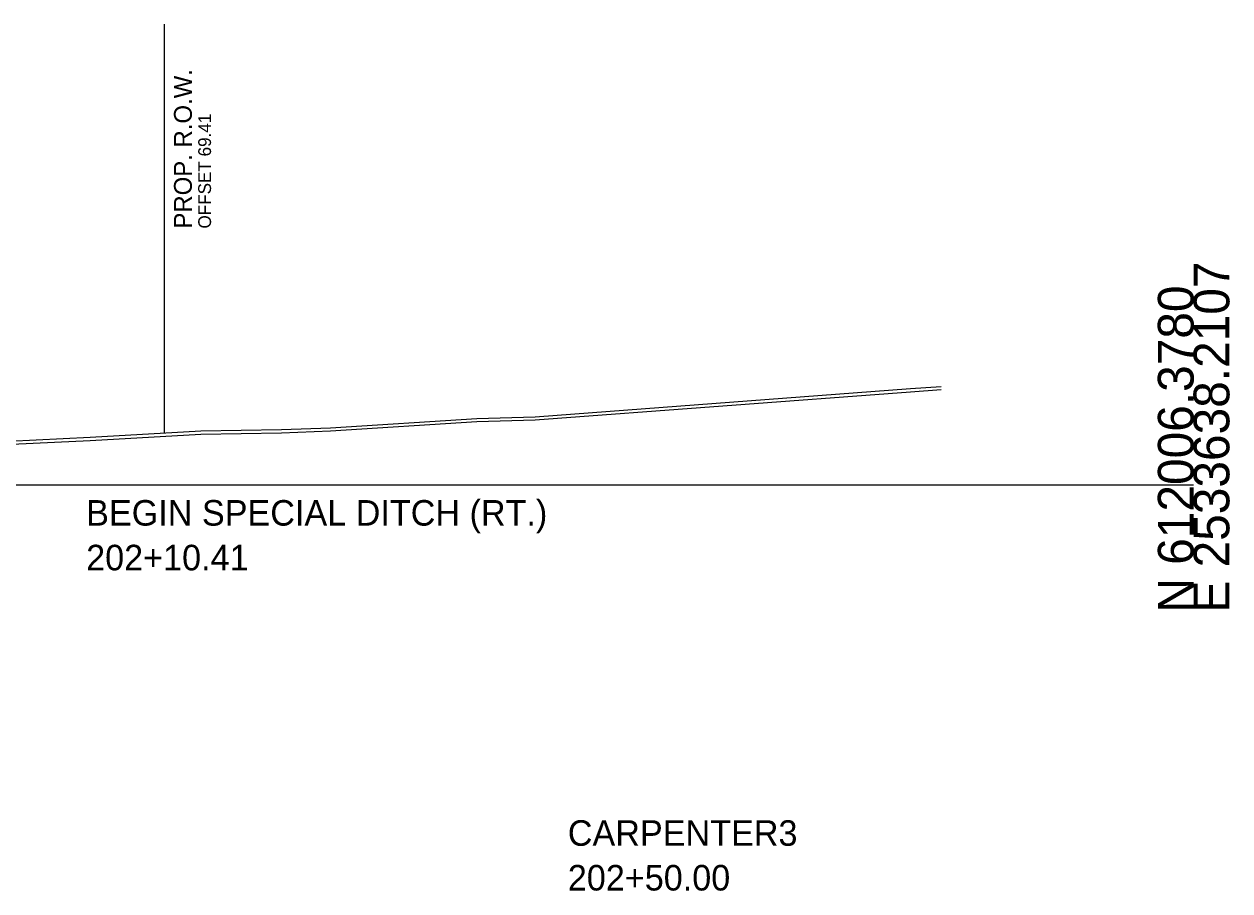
# Model space of a CAD drawing. Extents: x -120 to 2876, y -25 to 8560.
# Drawn here: x 208.4 to 302.8, y 4968.2 to 5036.1 of the extents above; entities that cross this region are included whole.
import ezdxf

# ---------------------------------------------------------------- set-up
doc = ezdxf.new("R2010")
doc.units = 0
for name, color, linetype in [('DESIGN - ROW - Right-of-Way and Easement Labels', 7, 'Continuous'), ('DESIGN - ROW - Right-of-Way Linework', 7, 'Continuous'), ('DESIGN - SHEET - Light Grid', 7, 'Continuous'), ('DESIGN - TRANSPORTATION - Text', 7, 'Continuous'), ('DESIGN - TYPICAL - Warning Text', 7, 'Continuous'), ('SURVEY - GROUND - Bottom of Topsoil Layer', 7, 'Continuous'), ('SURVEY - GROUND - Top of Ground', 7, 'Continuous')]:
    doc.layers.add(name, color=color, linetype=linetype)

msp = doc.modelspace()

# ---------------------------------------------------------------- linework, layer by layer
at = {"layer": 'DESIGN - ROW - Right-of-Way Linework'}
msp.add_line((219.413, 5004.063), (219.413, 5036.063), dxfattribs=at)
at = {"layer": 'DESIGN - SHEET - Light Grid'}
msp.add_line((150, 5000), (300, 5000), dxfattribs=at)
at = {"layer": 'SURVEY - GROUND - Bottom of Topsoil Layer'}
for p, q in [((248.444, 5005.081), (277.826, 5007.286)), ((277.826, 5007.286), (280.241, 5007.452)), ((232.411, 5004.225), (243.885, 5004.955)), ((243.885, 5004.955), (248.444, 5005.081)), ((213.608, 5003.475), (222.261, 5003.98)), ((222.261, 5003.98), (228.586, 5004.074)), ((228.586, 5004.074), (232.411, 5004.225)), ((205.127, 5003.074), (213.608, 5003.475))]:
    msp.add_line(p, q, dxfattribs=at)
at = {"layer": 'SURVEY - GROUND - Top of Ground'}
msp.add_lwpolyline([(205.127, 5003.324), (213.608, 5003.725), (222.261, 5004.23), (228.586, 5004.324), (232.411, 5004.475), (243.885, 5005.205), (248.444, 5005.331), (277.826, 5007.536), (280.241, 5007.702)], dxfattribs=at)

# ---------------------------------------------------------------- texts
at = {"layer": 'DESIGN - ROW - Right-of-Way and Easement Labels'}
for s, height, p in [('PROP. R.O.W.', 1.4, (221.563, 5020.063)), ('OFFSET 69.41', 1, (223.063, 5020.063))]:
    msp.add_text(s, height=height, rotation=90, dxfattribs=at).set_placement(p)
at = {"layer": 'DESIGN - SHEET - Light Grid'}
for s, p in [('E 2533638.2107', (302.8, 4990)), ('N 612006.3780', (300, 4990))]:
    msp.add_text(s, height=2.8, rotation=90, dxfattribs=at).set_placement(p)
at = {"layer": 'DESIGN - TRANSPORTATION - Text'}
for s, p in [('BEGIN SPECIAL DITCH (RT.)', (213.285, 4996.81)), ('202+10.41', (213.285, 4993.31))]:
    msp.add_text(s, height=2, rotation=360, dxfattribs=at).set_placement(p)
at = {"layer": 'DESIGN - TYPICAL - Warning Text'}
for s, p in [('CARPENTER3', (251, 4971.75)), ('202+50.00', (251, 4968.25))]:
    msp.add_text(s, height=2, dxfattribs=at).set_placement(p)

doc.saveas('drawing.dxf')
